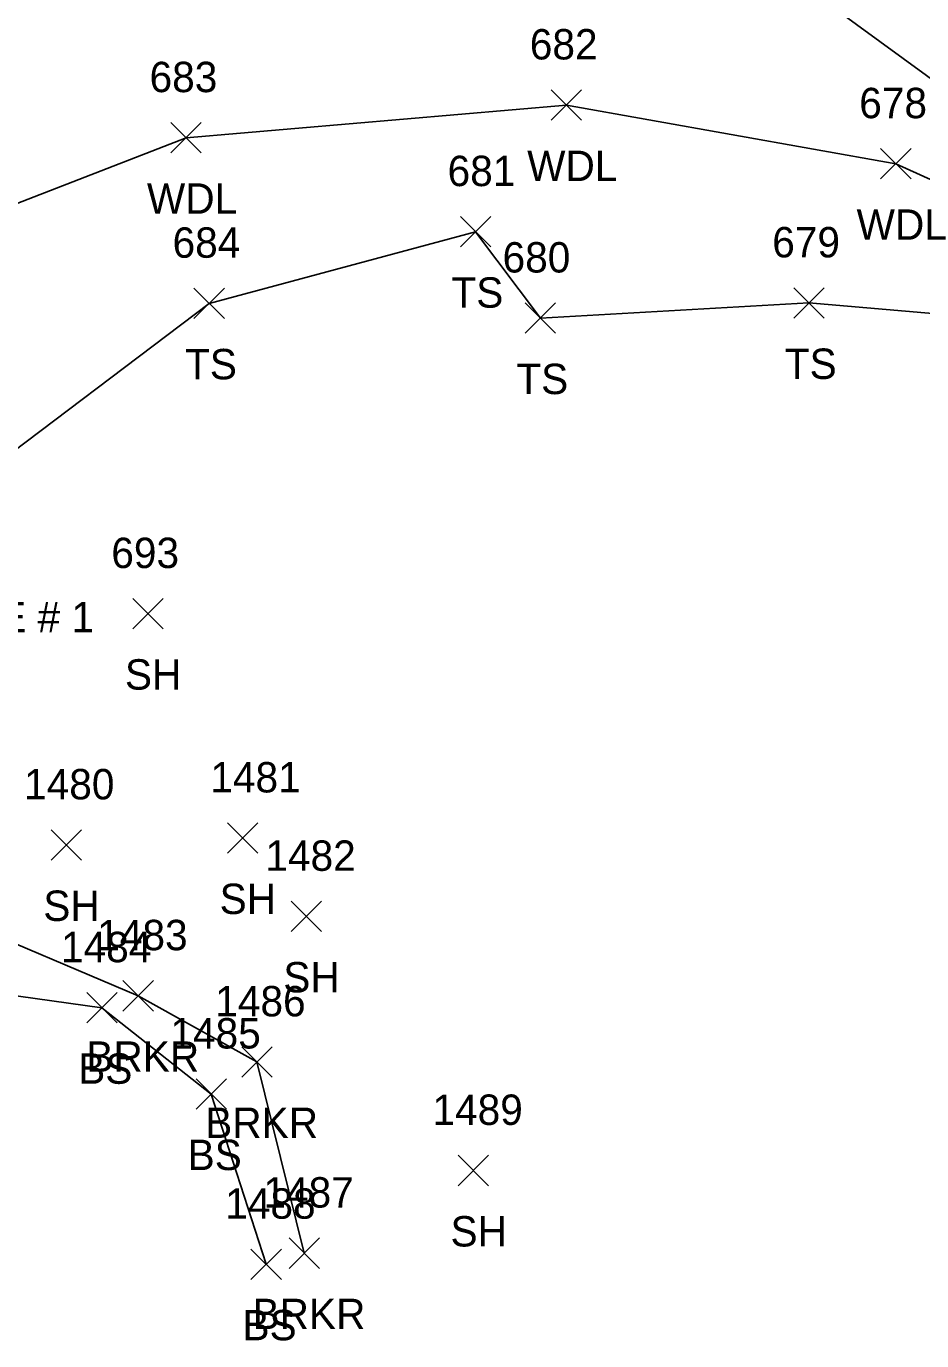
# Model space of a CAD drawing. Extents: x 1485624 to 1495982, y 886445 to 890805.
# Drawn here: x 1495744.5 to 1495803.4, y 890433.4 to 890519.9 of the extents above; entities that cross this region are included whole.
import ezdxf

# ---------------------------------------------------------------- set-up
doc = ezdxf.new("R2010")
doc.units = 0
for name, color, linetype in [('C_C', 7, 'Continuous'), ('L_A', 7, 'Continuous'), ('L_I', 7, 'Continuous'), ('L_TIC', 7, 'Continuous'), ('LAWA', 7, 'Continuous'), ('LAWE', 7, 'Continuous'), ('LELB', 7, 'Continuous')]:
    doc.layers.add(name, color=color, linetype=linetype)

msp = doc.modelspace()

# ---------------------------------------------------------------- linework, layer by layer
at = {"layer": 'L_TIC'}
for points in [[(1495779.011, 890513.68), (1495781.011, 890515.68)], [(1495781.011, 890513.68), (1495779.011, 890515.68)], [(1495753.978, 890511.528), (1495755.978, 890513.528)], [(1495755.978, 890511.528), (1495753.978, 890513.528)], [(1495800.699, 890509.814), (1495802.699, 890511.814)], [(1495802.699, 890509.814), (1495800.699, 890511.814)], [(1495773.033, 890505.345), (1495775.033, 890507.345)], [(1495775.033, 890505.345), (1495773.033, 890507.345)], [(1495755.493, 890500.631), (1495757.493, 890502.631)], [(1495757.493, 890500.631), (1495755.493, 890502.631)], [(1495794.979, 890500.656), (1495796.979, 890502.656)], [(1495796.979, 890500.656), (1495794.979, 890502.656)], [(1495777.305, 890499.659), (1495779.305, 890501.659)], [(1495779.305, 890499.659), (1495777.305, 890501.659)], [(1495751.46, 890480.211), (1495753.46, 890482.211)], [(1495753.46, 890480.211), (1495751.46, 890482.211)], [(1495746.086, 890464.99), (1495748.086, 890466.99)], [(1495748.086, 890464.99), (1495746.086, 890466.99)], [(1495757.694, 890465.445), (1495759.694, 890467.445)], [(1495759.694, 890465.445), (1495757.694, 890467.445)], [(1495761.886, 890460.287), (1495763.886, 890462.287)], [(1495763.886, 890460.287), (1495761.886, 890462.287)], [(1495750.819, 890455.062), (1495752.819, 890457.062)], [(1495752.819, 890455.062), (1495750.819, 890457.062)], [(1495748.432, 890454.274), (1495750.432, 890456.274)], [(1495750.432, 890454.274), (1495748.432, 890456.274)], [(1495758.642, 890450.71), (1495760.642, 890452.71)], [(1495760.642, 890450.71), (1495758.642, 890452.71)], [(1495755.634, 890448.595), (1495757.634, 890450.595)], [(1495757.634, 890448.595), (1495755.634, 890450.595)], [(1495772.894, 890443.567), (1495774.894, 890445.567)], [(1495774.894, 890443.567), (1495772.894, 890445.567)], [(1495761.758, 890438.128), (1495763.758, 890440.128)], [(1495763.758, 890438.128), (1495761.758, 890440.128)], [(1495759.245, 890437.395), (1495761.245, 890439.395)], [(1495761.245, 890437.395), (1495759.245, 890439.395)]]:
    msp.add_lwpolyline(points, dxfattribs=at)
at = {"layer": 'LAWA'}
msp.add_lwpolyline([(1495845.325, 890503.1), (1495828.066, 890498.904), (1495801.699, 890510.814), (1495780.011, 890514.68), (1495754.978, 890512.528), (1495737.495, 890505.743), (1495734.747, 890491.625)], dxfattribs=at)
at = {"layer": 'LAWE'}
msp.add_lwpolyline([(1495734.517, 890469.761), (1495739.7, 890461.203), (1495751.819, 890456.062), (1495759.642, 890451.71), (1495762.758, 890439.128)], dxfattribs=at)
at = {"layer": 'LELB'}
for points in [[(1495757.567, 890537.903), (1495788.353, 890527.831), (1495828.066, 890498.904), (1495795.979, 890501.656), (1495778.305, 890500.659), (1495774.033, 890506.345), (1495756.493, 890501.631), (1495740.745, 890489.731)], [(1495730.891, 890468.068), (1495736.094, 890457.13), (1495749.432, 890455.274), (1495756.634, 890449.595), (1495760.245, 890438.395)]]:
    msp.add_lwpolyline(points, dxfattribs=at)

# ---------------------------------------------------------------- texts
at = {"layer": 'C_C'}
msp.add_text('TOP OF STAKE # 1', height=2, dxfattribs=at).set_placement((1495724.988, 890479.985))
at = {"layer": 'L_A'}
for s, p in [('WDL', (1495777.428, 890509.68)), ('WDL', (1495752.396, 890507.528)), ('WDL', (1495799.116, 890505.814)), ('TS', (1495772.442, 890501.345)), ('TS', (1495754.902, 890496.631)), ('TS', (1495794.389, 890496.656)), ('TS', (1495776.714, 890495.659)), ('SH', (1495750.948, 890476.211)), ('SH', (1495757.182, 890461.445)), ('SH', (1495745.574, 890460.99)), ('SH', (1495761.374, 890456.287)), ('BRKR', (1495748.409, 890451.062)), ('BS', (1495747.873, 890450.274)), ('BRKR', (1495756.232, 890446.71)), ('BS', (1495755.075, 890444.595)), ('SH', (1495772.383, 890439.567)), ('BRKR', (1495759.348, 890434.128)), ('BS', (1495758.686, 890433.395))]:
    msp.add_text(s, height=2, dxfattribs=at).set_placement(p)
at = {"layer": 'L_I'}
for s, p in [('682', (1495777.602, 890517.68)), ('683', (1495752.569, 890515.528)), ('678', (1495799.289, 890513.814)), ('681', (1495772.19, 890509.345)), ('684', (1495754.083, 890504.631)), ('679', (1495793.562, 890504.656)), ('680', (1495775.809, 890503.659)), ('693', (1495750.051, 890484.211)), ('1481', (1495756.569, 890469.445)), ('1480', (1495744.307, 890468.99)), ('1482', (1495760.194, 890464.287)), ('1483', (1495749.126, 890459.062)), ('1484', (1495746.739, 890458.274)), ('1486', (1495756.894, 890454.71)), ('1485', (1495753.942, 890452.595)), ('1489', (1495771.194, 890447.567)), ('1487', (1495760.065, 890442.128)), ('1488', (1495757.552, 890441.395))]:
    msp.add_text(s, height=2, dxfattribs=at).set_placement(p)

doc.saveas('drawing.dxf')
